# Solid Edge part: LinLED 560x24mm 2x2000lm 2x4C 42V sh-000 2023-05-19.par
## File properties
Author: jaroslaw.przewlocki
Template: iso metric part.par
Last saved by: jaroslaw.przewlocki
Revision: 2
Application: Solid Edge
Gęstość: 0,000 kg/m^3
Dokładność: 0,990
Username: jaroslaw.przewlocki
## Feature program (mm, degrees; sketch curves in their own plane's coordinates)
body "unnamed Body 1"
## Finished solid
Body 1: solid body, 3746 faces, 9636 edges, 6192 vertices.
  Faces by surface: plane 2576, cylinder 546, torus 256, cone 200, spline 104, sphere 64
  Edges by curve: line 7152, curve on surface 1424, circle 652, ellipse 264, spline 144
Bounding box of the edges (mm; curved faces can reach further): 559.600 x 24.000 x 4.450, from (-279.8, -12, 0) to (279.8, 12, 4.45).
Cylindrical faces by radius (mm): R0.2 x184, R0.2169 x24, R0.25 x64, R0.3373 x24, R0.4 x32, R0.4006 x8, R0.4008 x8, R0.525 x8, R0.6 x80, R1 x32, R1.1 x16, R1.1989 x8, R1.199 x8, R1.2 x40, R2.15 x10
Conical faces (half-angle, radius in mm at the cone's reference point): 0.398 deg R1.1964 x8, 0.4493 deg R1.1964 x8, 0.4746 deg R1.1948 x8, 0.4758 deg R1.1948 x8, 0.5 deg R0.5056 x16, 0.5 deg R1.0082 x16, 1 deg R0.5511 x8, 10 deg R0.2132 x16, 10 deg R0.4132 x16, 16.0099 deg R1.1053 x8, 16.1249 deg R1.1279 x8, 18.8604 deg R1.0669 x16, 19.5041 deg R0.5138 x8, 19.8244 deg R0.5099 x8, 27.363 deg R0.6214 x8, 40.6434 deg R0.5161 x8, 43.3309 deg R0.4892 x8, 45 deg R0.575 x8, 45 deg R0.625 x16
Toroidal faces (ring radius, tube radius in mm): R0.0958 r0.3997 x16, R0.1076 r0.4 x8, R0.1101 r0.4001 x8, R0.1217 r0.4 x8, R0.1234 r0.4 x8, R0.1626 r0.228 x8, R0.1634 r0.2287 x8, R0.3287 r0.2001 x8, R0.3684 r0.2151 x8, R0.3703 r0.4 x8, R0.3818 r0.2 x16, R0.4166 r0.3983 x8, R0.5981 r0.197 x8, R0.5982 r0.197 x8, R0.6009 r0.3968 x8, R0.6009 r0.3969 x8, R0.6227 r0.2 x8, R0.6235 r0.2 x8, R0.8 r0.2 x16, R0.8522 r0.3 x8, R0.9002 r0.2 x8, R0.9018 r0.2 x8, R0.9197 r0.223 x8, R0.9365 r0.2 x8, R0.9663 r0.2263 x8, R0.9665 r0.2263 x8, R1.429 r1.2 x8, R1.8741 r0.2175 x8, R1.9007 r0.2 x8
Spherical faces by radius (mm): R0.2 x48, R0.6 x16
Planar faces by outward normal: +x 291, +y 295, +z 433, -x 291, -y 301, -z 33, oblique 932
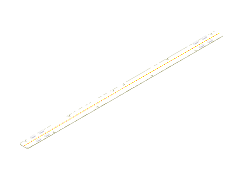
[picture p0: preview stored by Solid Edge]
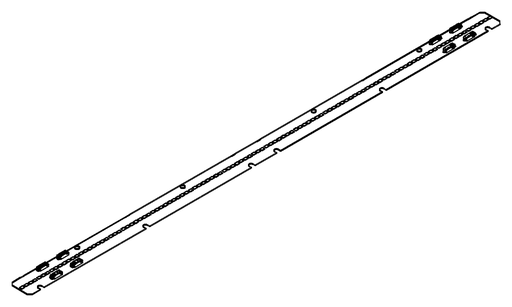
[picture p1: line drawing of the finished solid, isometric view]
